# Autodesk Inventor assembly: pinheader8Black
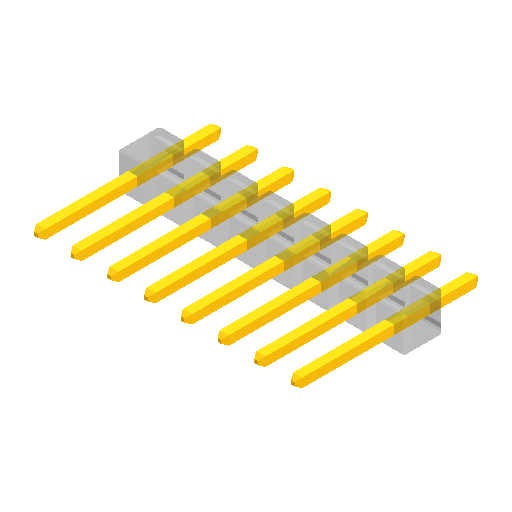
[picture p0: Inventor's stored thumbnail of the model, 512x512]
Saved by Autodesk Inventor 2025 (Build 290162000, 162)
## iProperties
Created: 2025-05
Part Number: pinheader8Black
Document SubType Name: Assembly
Designer: R5800u
Author: R5800u
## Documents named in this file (3)
- C:\Users\R5800u\Desktop\drone\c3\ESP32-C3 Super Mini breakout expansion board module -Assembly\pinheader8Black.iam
- C:\Users\R5800u\Desktop\drone\c3\ESP32-C3 Super Mini breakout expansion board module -Assembly\COMPOUND_4.iam
- C:\Users\R5800u\Desktop\drone\c3\ESP32-C3 Super Mini breakout expansion board module -Assembly\COMPOUND_5.iam
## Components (2 placed, 2 different names)
1. 48 [sub-assembly]
2. 57 [sub-assembly]
